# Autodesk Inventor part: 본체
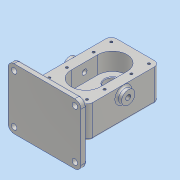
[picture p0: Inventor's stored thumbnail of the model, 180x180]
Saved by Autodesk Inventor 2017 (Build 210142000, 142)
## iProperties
Part Number: 본체
Material: 알루미늄 6061
Document SubType Name: Modeling
Designer: MRC
Density: 2.7 g/cm^3
Appearance: 알루미늄 - 평지
Mass: 1472.54 g
Surface Area: 818.394 cm^2
Volume: 545.387 cm^3
Author: MRC
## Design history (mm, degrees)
sketch "스케치1"
  geometry: L1 (-40, 38)-(40, 38); L2 (40, 38)-(40, -82); L3 (40, -82)-(-40, -82); L4 (-40, -82)-(-40, 38); C1 r 19 at (0, 0); 2 further points
  constraints: 8 end point, 2 parallel, 1 centre point, 1 coincident, 1 horizontal, 1 midpoint, 1 perpendicular, 1 vertical alignment
  dimensions: "d0" = 38 diameter of C1; "d1" = 80 distance of L1.start L1.end; "d2" = 120 distance of L1.end L2.end; "d3" = 38 distance of point (0, 0) point (0, 38)
extrude "돌출1" new body sketch "스케치1" distance "d4" = 14; taper "d5" = 0 deg
extrude "돌출2" join sketch "스케치1" distance "d6" = 39; taper "d7" = 0 deg
fillet "모깎기1" dims "d8" = 9
sketch "스케치2"
  geometry: L1 (-31, -82)-(31, -82) reference; L2 (31, 38)-(-31, 38) reference; L3 (-24, 0)-(-24, -44); L4 (24, 0)-(24, -44); A1 r 24 centre (0, 0) between (24, 0) and (-24, 0); A2 r 24 centre (0, -44) between (-24, -44) and (24, -44); 1 further point
  constraints: 4 end point, 4 point on circle, 2 centre point, 2 tangent, 1 coincident, 1 parallel
  dimensions: "d9" = 48 diameter of A1; "d10" = 48 diameter of A2; "d12" = 38 distance from line of A1.centre L2; "d13" = 38 distance from line of L1 A2.centre; "d14" = 92 dimension on A2 A1; "d15" = 48 distance between parallel lines of L4 L3
extrude "돌출3" cut sketch "스케치2" distance "d16" = 29; taper "d17" = 0 deg
sketch "스케치4"
  geometry: C1 r 19 at (0, 0); 1 further point
  constraints: 1 centre point, 1 coincident
  dimensions: "d18" = 38 diameter of C1
extrude "돌출4" join sketch "스케치4" distance "d19" = 17; taper "d20" = 0 deg
sketch "스케치6"
  geometry: C1 r 12.5 at (0, 0); C2 r 12.5 at (0, -44); A1 r 24 centre (0, 0) between (24, 0) and (-24, 0) reference; A2 r 24 centre (0, -44) between (-24, -44) and (24, -44) reference
  constraints: 2 centre point, 2 coincident
  dimensions: "d21" = 25 diameter of C1; "d22" = 25 diameter of C2
extrude "돌출5" cut sketch "스케치6" distance "d23" = 15; taper "d24" = 0 deg
hole "구멍1" diameter "d27" = 17; stored, may be unused: countersink angle "d31" = 90 deg, drill point angle "d33" = 0 deg; dims "d25" = 10, "d26" = 10, "d28" = 6, "d29" = 28, "d30" = 7.3, "d32" = 26
fillet "모깎기2" dims "d34" = 0.5
sketch "스케치8"
  geometry: L1 (0, -56)-(0, -55.3); L2 (14, -56)-(-14, -56) reference; L3 (0, -55.3)-(14, -55.3); L4 (14, -55.3)-(14.404, -56); L5 (-19, -56)-(19, -56) reference; L6 (0, -56)-(14.404, -56); L7 (-19, -56)-(19, -56) reference; L8 (19, -39)-(-19, -39) reference; L9 (14, -56)-(-14, -56) reference; L10 (-14, -49.2)-(14, -49.2) reference; L11 (14, -55.3)-(14, -56); L12 (14.404, -56)-(14, -56); 1 further point
  constraints: 12 end point, 1 collinear, 1 horizontal, 1 midpoint, 1 parallel, 1 perpendicular, 1 point on line
  dimensions: "d35" = 0.7 distance of L1.start L1.end; "d36" = 0.7 distance between parallel lines of L2 L3; "d40" = 60 deg angle of L5 L4
revolve "회전1" sketch "스케치8" stored, may be unused: angle "d41" = 90 deg
sketch "스케치9"
  geometry: A1 r 9 centre (-31, -73) between (-40, -73) and (-31, -82) reference; A2 r 9 centre (31, -73) between (31, -82) and (40, -73) reference; A3 r 9 centre (31, 29) between (40, 29) and (31, 38) reference; A4 r 9 centre (-31, 29) between (-31, 38) and (-40, 29) reference; 8 further points
  constraints: 4 coincident, 4 vertical alignment
  dimensions: "d42" = 29 distance of point (31, 0) point (31, 29); "d43" = 44 distance of point (31, -44) point (31, 0); "d44" = 29 distance of point (-31, 0) point (-31, 29); "d45" = 44 distance of point (-31, -44) point (-31, 0)
hole "구멍2" sketch "스케치9" at (-31, 29), (31, 29), (-31, 0), (-31, -44), (-31, -73), (31, -73), (31, -44), (31, 0) diameter "d46" = 4.134; stored, may be unused: countersink angle "d50" = 90 deg, drill point angle "d52" = 118 deg; dims "d47" = 10, "d48" = 28, "d49" = 7.3, "d51" = 12
sketch "스케치10"
  geometry: C1 r 11 at (-39, 51); 1 further point
  constraints: 1 centre point, 1 vertical alignment
  dimensions: "d53" = 22 diameter of C1; "d54" = 22 distance of C1.centre point (-39, 73)
extrude "돌출6" join sketch "스케치10" distance "d55" = 8; taper "d56" = 0 deg
hole "구멍3" diameter "d59" = 8.376; stored, may be unused: countersink angle "d63" = 90 deg, drill point angle "d65" = 118 deg; dims "d57" = 10, "d58" = 10, "d60" = 20, "d61" = 28, "d62" = 7.3, "d64" = 27.3
sketch "스케치12"
  geometry: L1 (-102, 44)-(-112, 44); L2 (-112, 44)-(-112, -56); L3 (-112, -56)-(-102, -56); L4 (-102, -56)-(-102, 44); L5 (-102, 14)-(-82, 2.453); L6 (-82, -27.453)-(-102, -39); L7 (38, 14)-(38, -39) reference; L8 (-19, -56)-(19, -56) reference; L9 (-82, -39)-(-82, 14) reference; 1 further point
  constraints: 12 end point, 5 point on line, 2 parallel, 1 horizontal, 1 perpendicular
  dimensions: "d69" = 150 distance between parallel lines of L7 L2; "d70" = 10 distance of L2.end L3.end; "d71" = 100 distance of L1.end L2.end; "d72" = 17 distance from line of L3 L6.end; "d73" = 53 distance of L5.start L6.end; "d74" = 60 deg angle of L6 L4; "d76" = 60 deg angle of L4 L5
extrude "돌출7" join sketch "스케치12" stored distance "d77" = 120; taper "d78" = 0 deg
extrude "돌출8" join sketch "스케치12" stored distance "d79" = 48; taper "d80" = 0 deg
fillet "모깎기3" dims "d81" = 10
fillet "모깎기4" dims "d82" = 3
fillet "모깎기5" dims "d83" = 3
sketch "스케치13"
  geometry: A1 r 7 centre (100, -7) between (107, -7) and (100, 0) reference; A2 r 7 centre (0, -7) between (0, 0) and (-7, -7) reference; A3 r 7 centre (0, -87) between (-7, -87) and (0, -94) reference; A4 r 7 centre (100, -87) between (100, -94) and (107, -87) reference; 5 further points
  constraints: 4 coincident
hole "구멍4" sketch "스케치13" at (0, -87), (0, -7), (100, -7), (100, -87) diameter "d84" = 9; stored, may be unused: countersink angle "d88" = 90 deg, drill point angle "d90" = 118 deg; dims "d85" = 20, "d86" = 28, "d87" = 7.3, "d89" = 27.3
fillet "모깎기6" dims "d91" = 3
sketch "스케치14"
  geometry: L1 (0, -97)-(100, -97) reference; L2 (-10, -7)-(-10, -87) reference; 2 further points
  constraints: 1 other
  dimensions: "d92" = 10 distance from line of point (50, -87) L1; "d93" = 60 distance from line of point (50, -87) L2
feature "엠보싱1" sketch "스케치14" dims "d9" = 48, "d10" = 48, "d12" = 38, "d13" = 38, "d14" = 92, "d15" = 48, "d94" = 0.5, "d95" = 0
chamfer "모따기1" distance "d96" = 1; stored, may be unused: second distance "d97" = 2, angle "d98" = 45 deg
node "솔리드1"
mirror "미러1"
node "투영된 루프1"
node "투영된 루프2"
